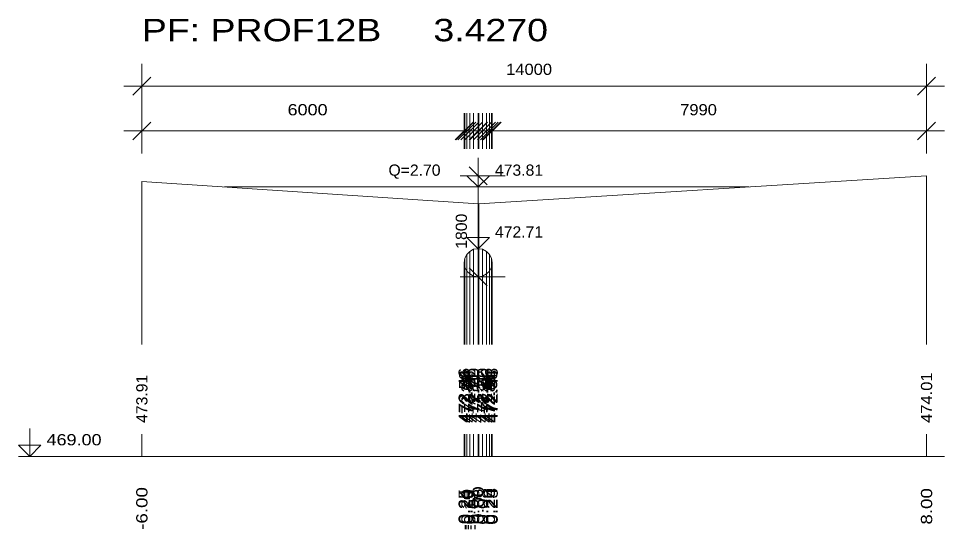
# Model space of a CAD drawing. Extents: x 7 to 442, y -393 to 441.
# Drawn here: x 413.84 to 430.36, y -244.33 to -235.22 of the extents above; entities that cross this region are included whole.
import ezdxf

# ---------------------------------------------------------------- set-up
doc = ezdxf.new("R2010")
doc.units = 0
doc.header["$LTSCALE"] = 0.08
doc.layers.add('7', color=7, linetype='Continuous', lineweight=13)

msp = doc.modelspace()

# ---------------------------------------------------------------- linework, layer by layer
at = {"layer": '7'}
for p, q in [((416.038, -237.628), (416.038, -236.028)), ((430.038, -237.628), (430.038, -236.028)), ((415.878, -236.588), (416.198, -236.268)), ((429.878, -236.588), (430.198, -236.268)), ((415.718, -236.428), (430.358, -236.428)), ((416.038, -237.548), (416.038, -236.908)), ((421.788, -237.548), (421.788, -236.908)), ((421.798, -237.548), (421.798, -236.908)), ((421.798, -237.548), (421.798, -236.908)), ((421.838, -237.548), (421.838, -236.908)), ((421.838, -237.548), (421.838, -236.908)), ((421.888, -237.548), (421.888, -236.908)), ((421.888, -237.548), (421.888, -236.908)), ((421.958, -237.548), (421.958, -236.908)), ((421.958, -237.548), (421.958, -236.908)), ((422.038, -237.548), (422.038, -236.908)), ((422.038, -237.548), (422.038, -236.908)), ((422.038, -237.548), (422.038, -236.908)), ((422.048, -237.548), (422.048, -236.908)), ((422.048, -237.548), (422.048, -236.908)), ((422.118, -237.548), (422.118, -236.908)), ((422.118, -237.548), (422.118, -236.908)), ((422.188, -237.548), (422.188, -236.908)), ((422.188, -237.548), (422.188, -236.908)), ((422.238, -237.548), (422.238, -236.908)), ((422.238, -237.548), (422.238, -236.908)), ((422.278, -237.548), (422.278, -236.908)), ((422.278, -237.548), (422.278, -236.908)), ((422.288, -237.548), (422.288, -236.908)), ((430.038, -237.548), (430.038, -236.908)), ((415.878, -237.388), (416.198, -237.068)), ((421.628, -237.388), (421.948, -237.068)), ((421.638, -237.388), (421.958, -237.068)), ((421.638, -237.388), (421.958, -237.068)), ((421.678, -237.388), (421.998, -237.068)), ((421.678, -237.388), (421.998, -237.068)), ((421.728, -237.388), (422.048, -237.068)), ((421.728, -237.388), (422.048, -237.068)), ((421.798, -237.388), (422.118, -237.068)), ((421.798, -237.388), (422.118, -237.068)), ((421.878, -237.388), (422.198, -237.068)), ((421.878, -237.388), (422.198, -237.068)), ((421.878, -237.388), (422.198, -237.068)), ((421.888, -237.388), (422.208, -237.068)), ((421.888, -237.388), (422.208, -237.068)), ((421.958, -237.388), (422.278, -237.068)), ((421.958, -237.388), (422.278, -237.068)), ((422.028, -237.388), (422.348, -237.068)), ((422.028, -237.388), (422.348, -237.068)), ((422.078, -237.388), (422.398, -237.068)), ((422.078, -237.388), (422.398, -237.068)), ((422.118, -237.388), (422.438, -237.068)), ((422.118, -237.388), (422.438, -237.068)), ((422.128, -237.388), (422.448, -237.068)), ((429.878, -237.388), (430.198, -237.068)), ((415.718, -237.228), (430.358, -237.228)), ((422.038, -239.988), (422.038, -237.708)), ((422.198, -238.188), (421.878, -237.868)), ((421.718, -238.028), (422.518, -238.028)), ((430.038, -241.034), (430.038, -238.028)), ((416.038, -241.034), (416.038, -238.128)), ((417.514, -238.226), (426.867, -238.226)), ((422.038, -241.034), (422.038, -238.528)), ((422.048, -241.034), (422.048, -238.528)), ((421.958, -241.034), (421.958, -239.338)), ((422.038, -241.034), (422.038, -239.328)), ((422.038, -239.328), (422.048, -239.328)), ((422.048, -241.034), (422.048, -239.328)), ((422.118, -241.034), (422.118, -239.338)), ((421.798, -241.034), (421.798, -239.498)), ((421.838, -241.034), (421.838, -239.428)), ((421.888, -241.034), (421.888, -239.378)), ((422.188, -241.034), (422.188, -239.378)), ((422.238, -241.034), (422.238, -239.428)), ((422.278, -241.034), (422.278, -239.498)), ((421.788, -241.034), (421.788, -239.578)), ((421.798, -241.034), (421.798, -239.658)), ((422.198, -239.988), (421.878, -239.668)), ((422.278, -241.034), (422.278, -239.658)), ((422.288, -241.034), (422.288, -239.578)), ((421.718, -239.828), (422.518, -239.828)), ((421.838, -241.034), (421.838, -239.728)), ((421.888, -241.034), (421.888, -239.778)), ((421.958, -241.034), (421.958, -239.818)), ((422.038, -241.034), (422.038, -239.828)), ((422.118, -241.034), (422.118, -239.818)), ((422.188, -241.034), (422.188, -239.778)), ((422.238, -241.034), (422.238, -239.728)), ((416.038, -243.034), (416.038, -242.634)), ((421.788, -243.034), (421.788, -242.634)), ((421.798, -243.034), (421.798, -242.634)), ((421.798, -243.034), (421.798, -242.634)), ((421.838, -243.034), (421.838, -242.634)), ((421.838, -243.034), (421.838, -242.634)), ((421.888, -243.034), (421.888, -242.634)), ((421.888, -243.034), (421.888, -242.634)), ((421.958, -243.034), (421.958, -242.634)), ((421.958, -243.034), (421.958, -242.634)), ((422.038, -243.034), (422.038, -242.634)), ((422.038, -243.034), (422.038, -242.634)), ((422.038, -243.034), (422.038, -242.634)), ((422.048, -243.034), (422.048, -242.634)), ((422.048, -243.034), (422.048, -242.634)), ((422.118, -243.034), (422.118, -242.634)), ((422.118, -243.034), (422.118, -242.634)), ((422.188, -243.034), (422.188, -242.634)), ((422.188, -243.034), (422.188, -242.634)), ((422.238, -243.034), (422.238, -242.634)), ((422.238, -243.034), (422.238, -242.634)), ((422.278, -243.034), (422.278, -242.634)), ((422.278, -243.034), (422.278, -242.634)), ((422.288, -243.034), (422.288, -242.634)), ((430.038, -243.034), (430.038, -242.634)), ((413.838, -243.034), (430.358, -243.034))]:
    msp.add_line(p, q, dxfattribs=at)
for points in [[(422.038, -237.726), (422.038, -238.226), (421.838, -238.026), (422.238, -238.026), (422.038, -238.226)], [(416.038, -238.128), (422.038, -238.528), (422.038, -239.328), (421.958, -239.338), (421.888, -239.378), (421.838, -239.428), (421.798, -239.498), (421.788, -239.578), (421.798, -239.658), (421.838, -239.728), (421.888, -239.778), (421.958, -239.818), (422.038, -239.828), (422.118, -239.818), (422.188, -239.778), (422.238, -239.728), (422.278, -239.658), (422.288, -239.578), (422.278, -239.498), (422.238, -239.428), (422.188, -239.378), (422.118, -239.338), (422.048, -239.328), (422.048, -238.528), (430.038, -238.028)], [(422.038, -238.828), (422.038, -239.328), (421.838, -239.128), (422.238, -239.128), (422.038, -239.328)], [(414.038, -242.534), (414.038, -243.034), (413.838, -242.834), (414.238, -242.834), (414.038, -243.034)]]:
    msp.add_lwpolyline(points, dxfattribs=at)

# ---------------------------------------------------------------- texts
for s, height, width, p in [('PF: PROF12B     3.4270', 0.4, 1.25, (416.038, -235.628)), ('14000', 0.2, 1.1, (422.538, -236.228)), ('6000', 0.2, 1.2, (418.638, -236.948)), ('7990', 0.2, 1.1, (425.643, -236.948)), ('Q=2.70', 0.2, 1.05, (420.438, -238.026)), ('473.81', 0.2, 1.05, (422.338, -238.026)), ('472.71', 0.2, 1.05, (422.338, -239.128)), ('469.00', 0.2, 1.2, (414.338, -242.834))]:
    msp.add_text(s, height=height, dxfattribs=dict(at, width=width)).set_placement(p)
for s, width, p in [('1800', 1.05, (421.838, -239.328)), ('472.46 ', 1.2, (421.888, -242.434)), ('472.54 ', 1.15, (421.898, -242.434)), ('472.38 ', 1.15, (421.898, -242.434)), ('472.66 ', 1.2, (421.988, -242.434)), ('472.26 ', 1.2, (421.988, -242.434)), ('472.70 ', 1.2, (422.058, -242.434)), ('472.22 ', 1.15, (422.058, -242.434)), ('472.70 ', 1.2, (422.218, -242.434)), ('472.22 ', 1.15, (422.218, -242.434)), ('472.26 ', 1.2, (422.288, -242.434)), ('472.66 ', 1.2, (422.288, -242.434)), ('472.54 ', 1.15, (422.378, -242.434)), ('472.38 ', 1.15, (422.378, -242.434)), ('472.46 ', 1.2, (422.388, -242.434)), ('473.91 ', 1.05, (416.138, -242.434)), ('472.61 ', 1.1, (421.938, -242.434)), ('472.31 ', 1.05, (421.938, -242.434)), ('473.51 ', 1.05, (422.138, -242.434)), ('472.71 ', 1.05, (422.138, -242.434)), ('472.21 ', 1.05, (422.138, -242.434)), ('472.71 ', 1.05, (422.148, -242.434)), ('473.51 ', 1.05, (422.148, -242.434)), ('472.61 ', 1.1, (422.338, -242.434)), ('472.31 ', 1.05, (422.338, -242.434)), ('474.01 ', 1.1, (430.138, -242.434)), (' -6.00 ', 1.25, (416.138, -244.434)), (' -0.25 ', 1.2, (421.888, -244.434)), (' -0.24 ', 1.2, (421.898, -244.434)), (' -0.24 ', 1.2, (421.898, -244.434)), (' -0.20 ', 1.2, (421.938, -244.434)), (' -0.20 ', 1.2, (421.938, -244.434)), (' -0.15 ', 1.15, (421.988, -244.434)), (' -0.15 ', 1.15, (421.988, -244.434)), (' -0.08 ', 1.2, (422.058, -244.434)), (' -0.08 ', 1.2, (422.058, -244.434)), ('  0.00 ', 1.3, (422.138, -244.434)), ('  0.00 ', 1.3, (422.138, -244.434)), ('  0.00 ', 1.3, (422.138, -244.434)), ('  0.08 ', 1.25, (422.218, -244.434)), ('  0.08 ', 1.25, (422.218, -244.434)), ('  0.20 ', 1.25, (422.338, -244.434)), ('  0.20 ', 1.25, (422.338, -244.434)), ('  0.24 ', 1.25, (422.378, -244.434)), ('  0.24 ', 1.25, (422.378, -244.434)), ('  0.25 ', 1.25, (422.388, -244.434)), ('  8.00 ', 1.25, (430.138, -244.434)), ('  0.01 ', 1.15, (422.148, -244.434)), ('  0.01 ', 1.15, (422.148, -244.434)), ('  0.15 ', 1.15, (422.288, -244.434)), ('  0.15 ', 1.15, (422.288, -244.434))]:
    msp.add_text(s, height=0.2, rotation=90, dxfattribs=dict(at, width=width)).set_placement(p)

doc.saveas('drawing.dxf')
